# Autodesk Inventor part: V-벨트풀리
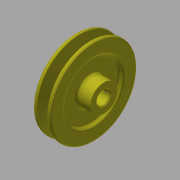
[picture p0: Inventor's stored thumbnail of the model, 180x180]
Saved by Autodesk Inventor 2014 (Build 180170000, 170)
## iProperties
Created: 2015-09
Part Number: V-벨트풀리
Material: 강철, 연강
Document SubType Name: Modeling
Designer: mduedu
Density: 7.86 g/cm^3
Mass: 779.014 g
Surface Area: 277.465 cm^2
Volume: 99.1112 cm^3
Appearance: 강철
Author: mduedu
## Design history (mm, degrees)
sketch "스케치1"
  geometry: L1 (-10, 0)-(10, 0); L2 (-10, 0)-(-10, 48); L3 (-10, 48)-(-5.976, 48); L4 (-5.976, 48)-(-2.154, 35.5); L5 (-2.154, 35.5)-(2.154, 35.5); L6 (2.154, 35.5)-(5.976, 48); L7 (5.976, 48)-(10, 48); L8 (10, 48)-(10, 0); L9 (0, 0)-(0, 35.5); L10 (-10, 43.5)-(10, 43.5); 3 further points
  constraints: 20 end point, 6 point on line, 3 perpendicular, 2 midpoint, 2 parallel, 2 symmetric about line, 1 coincident, 1 collinear, 1 equal length, 1 horizontal, 1 vertical, 1 vertical alignment
  dimensions: "d0" = 20 distance between parallel lines of L8 L2; "d2" = 96 diameter of L3 L1; "d3" = 87 diameter of L10 L1; "d4" = 4.5 distance between parallel lines of L10 L3 (derived); "d5" = 8 distance between parallel lines of L5 L10; "d6" = 9.2 distance of point (4.6, 43.5) point (-4.6, 43.5); "d7" = 34 deg angle of L6 L4
revolve "회전1" sketch "스케치1" stored, may be unused: angle "d8" = 90 deg
sketch "스케치2"
  geometry: C1 r 15 at (0, 0); 1 further point
  constraints: 1 centre point, 1 coincident
  dimensions: "d9" = 30 diameter of C1
extrude "돌출1" join sketch "스케치2" distance "d10" = 11; taper "d11" = 0 deg
fillet "모깎기1" dims "d12" = 1, "d13" = 0.5, "d14" = 2
sketch "스케치3"
  geometry: C1 r 15 at (0, 0) reference; C2 r 32 at (0, 0); 1 further point
  constraints: 1 centre point, 1 coincident
  dimensions: "d15" = 64 diameter of C2
extrude "돌출2" cut sketch "스케치3" distance "d16" = 4; taper "d17" = 0 deg
fillet "모깎기2" dims "d18" = 3
fillet "모깎기3" dims "d19" = 3
fillet "모깎기4" dims "d20" = 3
sketch "스케치4"
  geometry: C1 r 7.5 at (0, 0); 1 further point
  constraints: 1 centre point, 1 coincident
  dimensions: "d21" = 15 diameter of C1
extrude "돌출3" cut sketch "스케치4" stored distance "d22" = 4; taper "d23" = 0 deg
sketch "스케치5"
  geometry: L1 (-2.5, 7.071)-(2.5, 7.071); L2 (2.5, 7.071)-(2.5, 9.8); L3 (2.5, 9.8)-(-2.5, 9.8); L4 (-2.5, 9.8)-(-2.5, 7.071); A1 r 7.5 centre (0, 0) between (-2.5, 7.071) and (2.5, 7.071) reference; 2 further points
  constraints: 8 end point, 3 point on circle, 2 parallel, 1 horizontal, 1 perpendicular, 1 vertical alignment
  dimensions: "d24" = 5 distance of L2.end L3.end; "d26" = 17.3 distance from line of L3 point (0, -7.5)
extrude "돌출4" cut sketch "스케치5" stored distance "d27" = 4; taper "d28" = 0 deg
chamfer "모따기1" distance "d29" = 1; stored, may be unused: second distance "d30" = 2, angle "d31" = 45 deg
node "작업 평면1"
sketch "스케치6"
  geometry: L1 (-11, 15)-(-11, -15) reference; 2 further points
  constraints: 1 horizontal alignment
  dimensions: "d32" = 5 distance from line of point (-6, 0) L1
hole "구멍1" sketch "스케치6" at (-6, 0) diameter "d33" = 3.242; stored, may be unused: countersink angle "d37" = 90 deg, drill point angle "d39" = 118 deg; dims "d34" = 6, "d35" = 4, "d36" = 2, "d38" = 8
node "솔리드1"
mirror "대칭1"
